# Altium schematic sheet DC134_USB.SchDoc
size 431 x 279 mm; Date: Not shown in title block; ApprovedBy: Not shown in title block; CheckedBy: Not shown in title block; Author: Not shown in title block; CompanyName: Not shown in title block; Engineer: Not shown in title block; Organization: Not shown in title block; Address1: Not shown in title block; Address2: Not shown in title block; Address3: Not shown in title block; Address4: Not shown in title block; DocumentNumber: 5; Revision: Use project parameter SCH_Rev; SheetNumber: 5; SheetTotal: 9; PageSetup: Record=PageOptions¦CenterHorizontal=True¦CenterVertical=True¦PrintScale=1.00¦XCorrection=1.00¦YCorrection=1.00¦PrintKind=0¦BorderSize=5000000¦LeftOffset=0¦BottomOffset=0¦Orientation=2¦PaperLength=1000¦PaperWidth=1000¦Scale=100¦PaperSource=15¦PrintQuality=600¦MediaType=1¦DitherType=10¦PaperKind=Letter¦PrintScaleMode=1
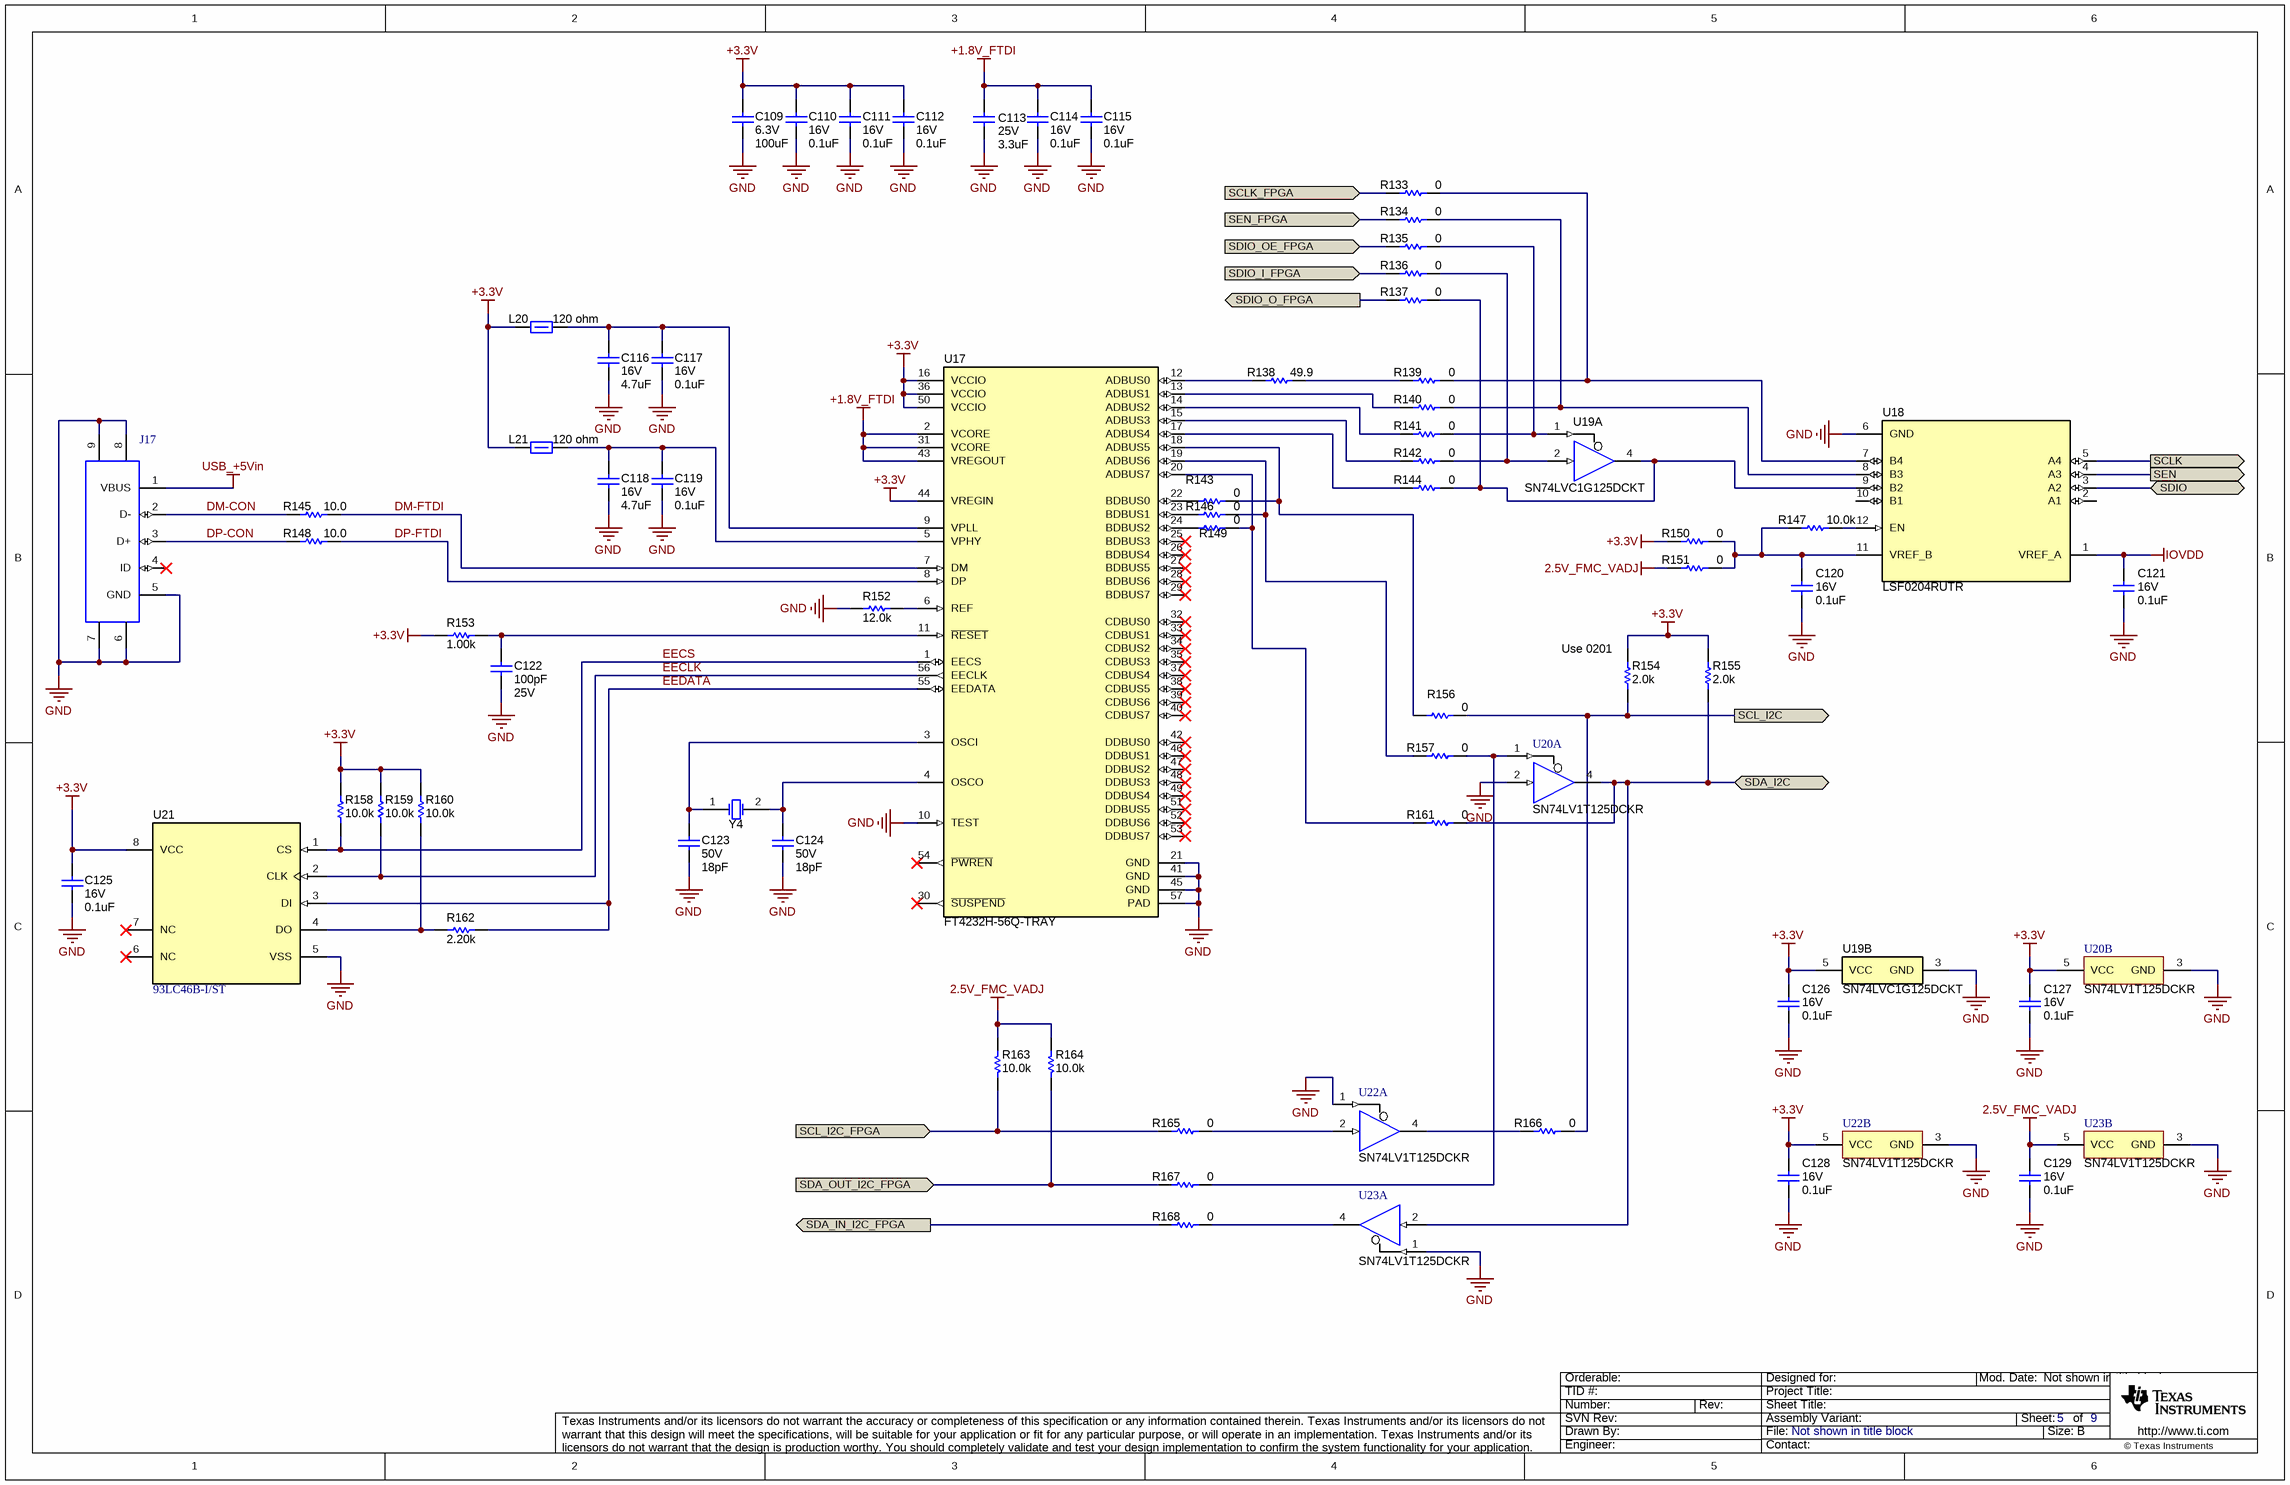
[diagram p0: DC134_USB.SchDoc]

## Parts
C109  VDC_V: 6.3V  ValueDisplayed: 100uF  [1206_190]  (hidden comment: C3216X5R0J107M160AB)
C110  VDC_V: 16V  ValueDisplayed: 0.1uF  [0201L]  (hidden comment: GRM033Z71C104KE14D)
C111  VDC_V: 16V  ValueDisplayed: 0.1uF  [0201L]  (hidden comment: GRM033Z71C104KE14D)
C112  VDC_V: 16V  ValueDisplayed: 0.1uF  [0201L]  (hidden comment: GRM033Z71C104KE14D)
C113  Value2: 25V  ValueDisplayed: 3.3uF  [0603]  (hidden comment: C1608X5R1E335K080AC)
C114  VDC_V: 16V  ValueDisplayed: 0.1uF  [0201L]  (hidden comment: GRM033Z71C104KE14D)
C115  VDC_V: 16V  ValueDisplayed: 0.1uF  [0201L]  (hidden comment: GRM033Z71C104KE14D)
C116  VDC_V: 16V  ValueDisplayed: 4.7uF  [0603]  (hidden comment: GRM188Z71C475KE21D)
C117  VDC_V: 16V  ValueDisplayed: 0.1uF  [0201L]  (hidden comment: GRM033Z71C104KE14D)
C118  VDC_V: 16V  ValueDisplayed: 4.7uF  [0603]  (hidden comment: GRM188Z71C475KE21D)
C119  VDC_V: 16V  ValueDisplayed: 0.1uF  [0201L]  (hidden comment: GRM033Z71C104KE14D)
C120  VDC_V: 16V  ValueDisplayed: 0.1uF  [0201L]  (hidden comment: GRM033Z71C104KE14D)
C121  VDC_V: 16V  ValueDisplayed: 0.1uF  [0201L]  (hidden comment: GRM033Z71C104KE14D)
C122  ValueDisplayed: 100pF  VDC_V: 25V  [0201L]  (hidden comment: CC0201JRNPO8BN101)
C123  VDC_V: 50V  ValueDisplayed: 18pF  [0402L]  (hidden comment: C1005C0G1H180J050BA)
C124  VDC_V: 50V  ValueDisplayed: 18pF  [0402L]  (hidden comment: C1005C0G1H180J050BA)
C125  VDC_V: 16V  ValueDisplayed: 0.1uF  [0201L]  (hidden comment: GRM033Z71C104KE14D)
C126  VDC_V: 16V  ValueDisplayed: 0.1uF  [0201L]  (hidden comment: GRM033Z71C104KE14D)
C127  VDC_V: 16V  ValueDisplayed: 0.1uF  [0201L]  (hidden comment: GRM033Z71C104KE14D)
C128  VDC_V: 16V  ValueDisplayed: 0.1uF  [0201L]  (hidden comment: GRM033Z71C104KE14D)
C129  VDC_V: 16V  ValueDisplayed: 0.1uF  [0201L]  (hidden comment: GRM033Z71C104KE14D)
J17  1734035-2  [CONN_USB-Mini-B-1734035-2]  (value not drawn)
L20  ValueDisplayed: 120 ohm  [0402]  (hidden comment: 74279271)
L21  ValueDisplayed: 120 ohm  [0402]  (hidden comment: 74279271)
R133  ValueDisplayed: 0  [0201L]  (hidden comment: CRCW02010000Z0ED)
R134  ValueDisplayed: 0  [0201L]  (hidden comment: CRCW02010000Z0ED)
R135  ValueDisplayed: 0  [0201L]  (hidden comment: CRCW02010000Z0ED)
R136  ValueDisplayed: 0  [0201L]  (hidden comment: CRCW02010000Z0ED)
R137  ValueDisplayed: 0  [0201L]  (hidden comment: CRCW02010000Z0ED)
R138  ValueDisplayed: 49.9  [0201L]  (hidden comment: RC0201FR-7D49R9L)
R139  ValueDisplayed: 0  [0201L]  (hidden comment: CRCW02010000Z0ED)
R140  ValueDisplayed: 0  [0201L]  (hidden comment: CRCW02010000Z0ED)
R141  ValueDisplayed: 0  [0201L]  (hidden comment: CRCW02010000Z0ED)
R142  ValueDisplayed: 0  [0201L]  (hidden comment: CRCW02010000Z0ED)
R143  ValueDisplayed: 0  [0201L]  (hidden comment: CRCW02010000Z0ED)
R144  ValueDisplayed: 0  [0201L]  (hidden comment: CRCW02010000Z0ED)
R145  ValueDisplayed: 10.0  [0402]  (hidden comment: RK73H1ETTP10R0F)
R146  ValueDisplayed: 0  [0201L]  (hidden comment: CRCW02010000Z0ED)
R147  ValueDisplayed: 10.0k  [0201L]  (hidden comment: RC0201FS-7D10KL)
R148  ValueDisplayed: 10.0  [0402]  (hidden comment: RK73H1ETTP10R0F)
R149  ValueDisplayed: 0  [0201L]  (hidden comment: CRCW02010000Z0ED)
R150  ValueDisplayed: 0  [0201L]  (hidden comment: CRCW02010000Z0ED)
R151  ValueDisplayed: 0  [0201L]  (hidden comment: CRCW02010000Z0ED)
R152  ValueDisplayed: 12.0k  [0201L]  (hidden comment: RC0201FR-7D12KL)
R153  ValueDisplayed: 1.00k  [0201L]  (hidden comment: RC0201FS-7D1KL)
R154  ValueDisplayed: 2.0k  [0402]  (hidden comment: CRCW04022K00JNED)
R155  ValueDisplayed: 2.0k  [0402]  (hidden comment: CRCW04022K00JNED)
R156  ValueDisplayed: 0  [0201L]  (hidden comment: CRCW02010000Z0ED)
R157  ValueDisplayed: 0  [0201L]  (hidden comment: CRCW02010000Z0ED)
R158  ValueDisplayed: 10.0k  [0201L]  (hidden comment: RC0201FR-7D10KL)
R159  ValueDisplayed: 10.0k  [0201L]  (hidden comment: RC0201FR-7D10KL)
R160  ValueDisplayed: 10.0k  [0201L]  (hidden comment: RC0201FR-7D10KL)
R161  ValueDisplayed: 0  [0201L]  (hidden comment: CRCW02010000Z0ED)
R162  ValueDisplayed: 2.20k  [0201L]  (hidden comment: RC0201FR-7D2K2L)
R163  ValueDisplayed: 10.0k  [0201L]  (hidden comment: RC0201FR-7D10KL)
R164  ValueDisplayed: 10.0k  [0201L]  (hidden comment: RC0201FR-7D10KL)
R165  ValueDisplayed: 0  [0201L]  (hidden comment: CRCW02010000Z0ED)
R166  ValueDisplayed: 0  [0201L]  (hidden comment: CRCW02010000Z0ED)
R167  ValueDisplayed: 0  [0201L]  (hidden comment: CRCW02010000Z0ED)
R168  ValueDisplayed: 0  [0201L]  (hidden comment: CRCW02010000Z0ED)
U17  FT4232H-56Q-TRAY  [VQFN-56]
U18  LSF0204RUTR  [RUT0012A]
U19  SN74LVC1G125DCKT  [DCK0005A_N]  (parts A,B of 2)
U20  SN74LV1T125DCKR  [DCK0005A_N]  (parts A,B of 2)
U21  93LC46B-I/ST  [TSSOP-8]
U22  SN74LV1T125DCKR  [DCK0005A_N]  (parts A,B of 2)
U23  SN74LV1T125DCKR  [DCK0005A_N]  (parts A,B of 2)
Y4  ABM3-12.000MHZ-D2Y-T  [XTAL_ABM3]  (value not drawn)

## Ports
SCL_I2C (out), SCL_I2C_FPGA (in), SCLK (out), SCLK_FPGA (in), SDA_I2C (bidir), SDA_IN_I2C_FPGA (out), SDA_OUT_I2C_FPGA (in), SDIO (bidir), SDIO_I_FPGA (in), SDIO_O_FPGA (out), SDIO_OE_FPGA (in), SEN (out), SEN_FPGA (in)

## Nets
2.5V_FMC_VADJ: C129.1 R151.1 R163.1 R164.1 U23.5(VCC)
+1.8V_FTDI: C113.1 C114.2 C115.2 U17.2(VCORE) U17.31(VCORE) U17.43(VREGOUT)
+3.3V: C109.1 C110.2 C111.2 C112.2 C125.2 C126.1 C127.1 C128.1 L20.1 L21.1 R150.1 R153.1 R154.2 R155.2 R158.2 R159.2 R160.2 U17.16(VCCIO) U17.36(VCCIO) U17.44(VREGIN) U17.50(VCCIO) U19.5(VCC) U20.5(VCC) U21.8(VCC) U22.5(VCC)
GND: C109.2 C110.1 C111.1 C112.1 C113.2 C114.1 C115.1 C116.2 C117.1 C118.2 C119.1 C120.2 C121.2 C122.2 C123.2 C124.2 C125.1 C126.2 C127.2 C128.2 C129.2 J17.5(GND) J17.6 J17.7 J17.8 J17.9 R152.1 U17.10(TEST) U17.21(GND) U17.41(GND) U17.45(GND) U17.57(PAD) U18.6(GND) U19.3(GND) U20.2(A) U20.3(GND) U21.5(VSS) U22.1(~{OE}) U22.3(GND) U23.1(~{OE}) U23.3(GND)
IOVDD: C121.1 U18.1(VREF_A)
USB_+5Vin: J17.1(VBUS)
DM-CON: J17.2(D-) R145.1
DM-FTDI: R145.2 U17.7(DM)
DP-CON: J17.3(D+) R148.1
DP-FTDI: R148.2 U17.8(DP)
EECLK: R159.1 U17.56(EECLK) U21.2(CLK)
EECS: R158.1 U17.1(EECS) U21.1(CS)
EEDATA: R162.2 U17.55(EEDATA) U21.3(DI)
SCL_I2C: R154.1 R156.2 R166.2 ; port SCL_I2C
SCL_I2C_FPGA: R163.2 R165.1 ; port SCL_I2C_FPGA
SCLK: U18.5(A4) ; port SCLK
SCLK_FPGA: R133.1 ; port SCLK_FPGA
SDA_I2C: R155.1 R161.2 U20.4(Y) U23.2(A) ; port SDA_I2C
SDA_IN_I2C_FPGA: R168.1 ; port SDA_IN_I2C_FPGA
SDA_OUT_I2C_FPGA: R164.2 R167.1 ; port SDA_OUT_I2C_FPGA
SDIO: U18.3(A2) ; port SDIO
SDIO_I_FPGA: R136.1 ; port SDIO_I_FPGA
SDIO_O_FPGA: R137.1 ; port SDIO_O_FPGA
SDIO_OE_FPGA: R135.1 ; port SDIO_OE_FPGA
SEN: U18.4(A3) ; port SEN
SEN_FPGA: R134.1 ; port SEN_FPGA
NetC116_1: C116.1 C117.2 L20.2 U17.9(VPLL)
NetC118_1: C118.1 C119.2 L21.2 U17.5(VPHY)
NetC120_1: C120.1 R147.2 R150.2 R151.2 U18.11(VREF_B)
NetC122_1: C122.1 R153.2 U17.11(~{RESET})
NetC123_1: C123.1 U17.3(OSCI) Y4.1(OSC1)
NetC124_1: C124.1 U17.4(OSCO) Y4.2(OSC2)
NetR133_2: R133.2 R139.2 U18.7(B4)
NetR134_2: R134.2 R140.2 U18.8(B3)
NetR135_2: R135.2 R141.2 U19.1(~{OE})
NetR136_2: R136.2 R142.2 U19.2(A)
NetR137_2: R137.2 R144.2 U18.9(B2) U19.4(Y)
NetR138_1: R138.1 U17.12(ADBUS0)
NetR138_2: R138.2 R139.1
NetR140_1: R140.1 U17.13(ADBUS1)
NetR141_1: R141.1 U17.14(ADBUS2)
NetR142_1: R142.1 U17.15(ADBUS3)
NetR143_1: R143.1 U17.22(BDBUS0)
NetR143_2: R143.2 R156.1 U17.18(ADBUS5)
NetR144_1: R144.1 U17.17(ADBUS4)
NetR146_1: R146.1 U17.23(BDBUS1)
NetR146_2: R146.2 R157.1 U17.19(ADBUS6)
NetR147_1: R147.1 U18.12(EN)
NetR149_1: R149.1 U17.24(BDBUS2)
NetR149_2: R149.2 R161.1 U17.20(ADBUS7)
NetR152_2: R152.2 U17.6(REF)
NetR157_2: R157.2 R167.2 U20.1(~{OE})
NetR160_1: R160.1 R162.1 U21.4(DO)
NetR165_2: R165.2 U22.2(A)
NetR166_1: R166.1 U22.4(Y)
NetR168_2: R168.2 U23.4(Y)

Not connected (* = marked no-connect by the designer): J17 4(ID)*; U17 25(BDBUS3)* 26(BDBUS4)* 27(BDBUS5)* 28(BDBUS6)* 29(BDBUS7)* 30(~{SUSPEND})* 32(CDBUS0)* 33(CDBUS1)* 34(CDBUS2)* 35(CDBUS3)* 37(CDBUS4)* 38(CDBUS5)* 39(CDBUS6)* 40(CDBUS7)* 42(DDBUS0)* 46(DDBUS1)* 47(DDBUS2)* 48(DDBUS3)* 49(DDBUS4)* 51(DDBUS5)* 52(DDBUS6)* 53(DDBUS7)* 54(~{PWREN})*; U18 2(A1) 10(B1); U21 6(NC)* 7(NC)*

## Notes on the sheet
- (near R154) Use 0201

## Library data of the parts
C109 = CMP-0064957-2: CAP, CERM, 100 uF, 6.3 V,+/- 20%, X5R, 1206; Manufacturer: TDK; TaMin_C: -55°C; Polarized: N; SizeAreaWB_mm2: 10.92; Value1: Unknown; U/M: EA; Value: 100uF; TaMax_C: 85°C; SizeZ_mm: 1.9; SizeX_mm: 3.2; SizeY_mm: 1.6; Cap_Case: 1206; SizeArea_mm2: 5.12; Cap_F: 100µF; AEC Category: Q200
C110-C112 C114 C115 C117 C119 C125 = CMP-0064970-1: CAP, CERM, 0.1 uF, 16 V,+/- 10%, X7R, 0201; Manufacturer: MuRata; TaMin_C: -55°C; Polarized: N; SizeAreaWB_mm2: 2.08; Value1: Unknown; U/M: EA; Value: 0.1uF; TaMax_C: 125°C; SizeZ_mm: 0.26; SizeX_mm: 0.6; SizeY_mm: 0.3; Cap_Case: 0201; SizeArea_mm2: 0.18; Cap_F: 100nF; AEC Category: Q200
C113 = CMP-0007008-5: CAP, CERM, 3.3 uF, 25 V, +/- 10%, X5R, 0603; Manufacturer: TDK; TaMin_C: -55°C; Polarized: N; SizeAreaWB_mm2: 4.68; Value1: Unknown; U/M: EA; Value: 3.3uF; TaMax_C: 85°C; SizeZ_mm: 1; SizeX_mm: 1.6; SizeY_mm: 0.8; SizeArea_mm2: 1.28; Cap_F: 3.3µF; AEC Category: Q200
C116 C118 = CMP-0064936-4: CAP, CERM, 4.7 uF, 16 V,+/- 10%, X7R, 0603; Manufacturer: MuRata; TaMin_C: -55°C; Polarized: N; SizeAreaWB_mm2: 4.68; Value1: Unknown; U/M: EA; Value: 4.7uF; TaMax_C: 125°C; SizeZ_mm: 1; SizeX_mm: 1.6; SizeY_mm: 0.8; SizeArea_mm2: 1.28; Cap_F: 4.7µF; AEC Category: Q200
C120 C121 C126-C129 = CMP-0064970-1: CAP, CERM, 0.1 uF, 16 V,+/- 10%, X7R, 0201; Manufacturer: MuRata; TaMin_C: -55°C; Polarized: N; SizeAreaWB_mm2: 2.08; Value1: Unknown; U/M: EA; Value: 0.1uF; TaMax_C: 125°C; SizeZ_mm: 0.26; SizeX_mm: 0.6; SizeY_mm: 0.3; Cap_Case: 0201; SizeArea_mm2: 0.18; CompType: Capacitor; Cap_F: 100nF; AEC Category: Q200
C122 = CMP-0085847-1: CAP, CERM, 100 pF, 25 V,+/- 5%, C0G/NP0, 0201; Manufacturer: Yageo; Polarized: N; Cap_Case: 0201; SizeX_mm: 0.6; TaMin_C: -55°C; AEC Category: Q200; SizeY_mm: 0.3; SizeZ_mm: 0.26; Value: 100pF; U/M: EA; SizeAreaWB_mm2: 2.08; TaMax_C: 125°C; SizeArea_mm2: 0.18
C123 C124 = CMP-0006247-2: CAP, CERM, 18 pF, 50 V, +/- 5%, C0G/NP0, 0402; Manufacturer: TDK; TaMin_C: -55°C; Polarized: N; SizeAreaWB_mm2: 3; Value1: Unknown; U/M: EA; Value: 18pF; TaMax_C: 125°C; SizeZ_mm: 0.6; SizeX_mm: 1; SizeY_mm: 0.5; Cap_Case: 0402; AEC Category: Q200
J17 = CMP-0054920-3: Connector, Receptacle, Mini-USB Type B, R/A, Top Mount SMT; Manufacturer: TE Connectivity; Green_Lifecycle: Active; Gender: Female; Green_REACh: Incomplete; CompType: USB
L20 L21 = CMP-0003214-1: Ferrite Bead, 120 ohm @ 100 MHz, 0.5 A, 0402; Manufacturer: Wurth Elektronik; Ztyp@1GHz_Ohm: 175.42; ZTyp@100MHz_Ohm: 120; SizeAreaWB_mm2: 3; DCR_ohm: 2d; Value1: 0.2 ohm; Value: 120 ohm; Imax_A: 5dA; SizeZ_mm: 0.6; SizeX_mm: 1; SizeY_mm: 0.5; Value2: 0.5A
R133-R137 R139-R144 R146 R149-R151 R156 R157 R161 R165-R168 = CMP-0027008-4: RES, 0, 5%, 0.05 W, 0201; Manufacturer: Vishay-Dale; Power_W: 50mW; TempCo: ppm/C; Value_Code: 0000; Value: 0; EIA_Code: E24; SizeX_mm: 0.6; SizeY_mm: 0.3; SizeZ_mm: 0.26; Value2: 0.05W; SizeArea_mm2: 0.18; CompType: Resistor; AEC Qualified: N; AEC Category: Q200
R138 = CMP-0028028-1: RES, 49.9, 1%, 0.05 W, 0201; Manufacturer: Yageo America; Power_W: 50mW; TempCo: 200 ppm/C; Value_Code: 49R9; U/M: EA; Value: 49.9; EIA_Code: E96; SizeX_mm: 0.6; SizeY_mm: 0.3; SizeZ_mm: 0.26; Value2: 0.05W; SizeArea_mm2: 0.18; AEC Qualified: N; VDC_V: 25V; AEC Category: Q200
R145 R148 = CMP-0026749-1: RES, 10.0, 1%, 0.063 W, 0402; Manufacturer: KOA Speer; Power_W: 63mW; TempCo: 100 ppm/C; Value_Code: 10R0; U/M: EA; Value: 10.0; EIA_Code: E96; Res_ohm: 10; SizeX_mm: 1; SizeY_mm: 0.5; SizeZ_mm: 0.6; Value2: 0.063W; AEC Qualified: N; VDC_V: 50V; AEC Category: Q200
R147 = CMP-0028071-1: RES, 10.0 k, 1%, 0.05 W, 0201; Manufacturer: Yageo America; Power_W: 50mW; TempCo: 200 ppm/C; Value_Code: 10k0; U/M: EA; Value: 10.0k; EIA_Code: E96; Res_ohm: 10k; SizeX_mm: 0.6; SizeY_mm: 0.3; SizeZ_mm: 0.26; Value2: 0.05W; SizeArea_mm2: 0.18; CompType: Resistor; AEC Qualified: N; VDC_V: 25V; AEC Category: Q200
R152 = CMP-0027954-1: RES, 12.0 k, 1%, 0.05 W, 0201; Manufacturer: Yageo America; Power_W: 50mW; TempCo: 200 ppm/C; Value_Code: 12k0; U/M: EA; Value: 12.0k; Res_ohm: 12k; SizeX_mm: 0.6; SizeY_mm: 0.3; SizeZ_mm: 0.26; Value2: 0.05W; SizeArea_mm2: 0.18; CompType: Resistor; AEC Qualified: N; VDC_V: 25V; AEC Category: Q200
R153 = CMP-0028084-1: RES, 1.00 k, 1%, 0.05 W, 0201; Manufacturer: Yageo America; Power_W: 50mW; TempCo: 200 ppm/C; Value_Code: 1k00; U/M: EA; Value: 1.00k; EIA_Code: E96; Res_ohm: 1k; SizeX_mm: 0.6; SizeY_mm: 0.3; SizeZ_mm: 0.26; Value2: 0.05W; SizeArea_mm2: 0.18; AEC Qualified: N; VDC_V: 25V; AEC Category: Q200
R154 R155 = CMP-0026889-5: RES, 2.0 k, 5%, 0.063 W, AEC-Q200 Grade 0, 0402; Manufacturer: Vishay-Dale; Power_W: 63mW; TempCo: 200 ppm/C; Value_Code: 2k00; Value: 2.0k; EIA_Code: E24; Res_ohm: 2k; SizeX_mm: 1; SizeY_mm: 0.5; SizeZ_mm: 0.6; Value2: 0.063W; AEC Qualified: Y; VDC_V: 50V; AEC Category: Q200; AEC Grade: 0
R158-R160 R163 = CMP-0027945-1: RES, 10.0 k, 1%, 0.05 W, 0201; Manufacturer: Yageo America; Power_W: 50mW; TempCo: 200 ppm/C; Value_Code: 10k0; U/M: EA; Value: 10.0k; EIA_Code: E96; Res_ohm: 10k; SizeX_mm: 0.6; SizeY_mm: 0.3; SizeZ_mm: 0.26; Value2: 0.05W; SizeArea_mm2: 0.18; AEC Qualified: N; VDC_V: 25V; AEC Category: Q200
R162 = CMP-0027995-1: RES, 2.20 k, 1%, 0.05 W, 0201; Manufacturer: Yageo America; Power_W: 50mW; TempCo: 200 ppm/C; Value_Code: 2k20; U/M: EA; Value: 2.20k; Res_ohm: 2.2k; SizeX_mm: 0.6; SizeY_mm: 0.3; SizeZ_mm: 0.26; Value2: 0.05W; SizeArea_mm2: 0.18; AEC Qualified: N; VDC_V: 25V; AEC Category: Q200
R164 = CMP-0027945-1: RES, 10.0 k, 1%, 0.05 W, 0201; Manufacturer: Yageo America; Power_W: 50mW; TempCo: 200 ppm/C; Value_Code: 10k0; U/M: EA; Value: 10.0k; EIA_Code: E96; Res_ohm: 10k; SizeX_mm: 0.6; SizeY_mm: 0.3; SizeZ_mm: 0.26; Value2: 0.05W; SizeArea_mm2: 0.18; CompType: Resistor; AEC Qualified: N; VDC_V: 25V; AEC Category: Q200
U17 = CMP-0081661-1: Future Technology Devices International Ltd FT4232H Quad High Speed USB to Multipurpose UART/MPSSE IC, VQFN-56; Manufacturer: FTDI; SizeZ_mm: 1; SizeX_mm: 8; SizeArea_mm2: 64; SizeAreaWB_mm2: 100
U18 = CMP-0066443-2: 4-Bit Bidirectional Multi-Voltage Level Translator for Open-Drain & Push- Pull, RUT0012A (UQFN-12); Manufacturer: Texas Instruments; SizeZ_mm: 0.55; SizeX_mm: 1.7; SizeY_mm: 2.0; SizeArea_mm2: 3.4; CompType: IC; U/M: EA; SizeAreaWB_mm2: 8.1
U19 = CMP-0051305-3: Single Bus Buffer Gate With 3-State Outputs, DCK0005A, SMALL T&R; Manufacturer: Texas Instruments; Output Type: CMOS; tpd @ Nom Voltage(Max)(ns): 9,5.5,4.5,4; VCC(Max)(V): 5.5; 3-State Output: Yes; VCC(Min)(V): 1.65; Input Type: CMOS/TTL; Rating: Catalog; Sub-Family: Non-Inverting Buffer/Driver; F @ Nom Voltage(Max)(Mhz): 150; Bits(#): 1; Schmitt Trigger: No; Voltage(Nom)(V): 1.8,2.5,3.3,5; Output Drive (IOL/IOH)(Max)(mA): 32/-32; Technology Family: LVC; ICC @ Nom Voltage(Max)(mA): 0.01; Logic: True; AEC Category: Q200; AEC Qualified: N; CompType: IC; SizeAreaWB_mm2: 9.3; SizeArea_mm2: 4.2; SizeX_mm: 2.1; SizeY_mm: 2.0; SizeZ_mm: 1.1
U20 U22 U23 = CMP-0051325-2: Single Power Supply, Single BUFFER GATE w/ 3-State Output (active low enable), DCK0005A, LARGE T&R; Manufacturer: Texas Instruments; tpd @ Nom Voltage(Max)(ns): 14.5,9.5,8.0,6.5; Output Drive (IOL/IOH)(Max)(mA): 8/-8; Voltage(Nom)(V): 1.8,2.5,3.3,5.5; Bits(#): 1; Rating: Catalog; Output Type: CMOS; Technology Family: LV1T; 3-State Output: Yes; Sub-Family: Non-Inverting Buffer/Driver; Logic: True; Input Type: TTL; Schmitt Trigger: No; VCC(Min)(V): 1.6; Special Features: 1.8V to 3.3V Up Translation,3.3V to 1.8V Down Translation,5V Input Tolerant; VCC(Max)(V): 5.5; ICC @ Nom Voltage(Max)(mA): 0.01; F @ Nom Voltage(Max)(Mhz): 50; AEC Category: Q200; AEC Qualified: N; CompType: IC; SizeAreaWB_mm2: 9.3; SizeArea_mm2: 4.2; SizeX_mm: 2.1; SizeY_mm: 2.0; SizeZ_mm: 1.1
U21 = CMP-0081524-1: 1K Microwire Compatible Serial EEPROM, TSSOP-8; Manufacturer: Microchip; SizeArea_mm2: 19.2; SizeAreaWB_mm2: 42; SizeY_mm: 3; SizeZ_mm: 1.2; SizeX_mm: 6.4
Y4 = CMP-0004616-3: Crystal, 12 MHz, 18 pF, SMD; Manufacturer: Abracon Corporation; TaMin_C: -40°C; Frequency Stability: +/-30ppm; Frequency_Fixed: 12MHz; TaMax_C: 85°C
